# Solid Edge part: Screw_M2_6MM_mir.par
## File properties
Last saved by: hhakima
Revision: 57
Density: 7750.000 kg/m^3
Accuracy: 0.990
Material: Stainless steel
Face Style: Steel
Fill Style: ANSI32(Steel)
Virtual Style: Stainless steel
Coef. of Thermal Exp: 1.6e-05
Thermal Conductivity: 17.0
Specific Heat: 502.0
Modulus of Elasticity: 193053196000.0
Poission's Ratio: 0.29
Yield Stress: 310264065.0
Ultimate Stress: 641212401.0
Elongation: 0.0
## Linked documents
Screw_M2_6MM.par
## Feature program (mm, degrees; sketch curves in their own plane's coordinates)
part copy "CopiedPart_1"
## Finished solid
Body 1: solid body, 24 faces, 41 edges, 20 vertices.
  Faces by surface: plane 10, cone 9, cylinder 3, spline 2
  Edges by curve: circle 15, line 12, intersection 10, spline 4
Bounding box of the edges (mm; curved faces can reach further): 3.800 x 3.800 x 8.000, from (-1.9, -1.9, -8) to (1.9, 1.9, 0).
Cylindrical faces by radius (mm): R0.7402 x1, R1 x1, R1.9 x1
Conical faces (half-angle, radius in mm at the cone's reference point): 45 deg R0.866 x6, 45 deg R1.71 x1, 45 deg R1.9 x1, 55 deg R0.4862 x1
Planar faces by outward normal: +x 1, +z 2, -x 1, -z 2, oblique 4
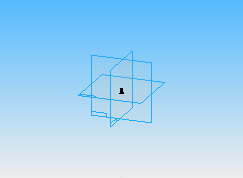
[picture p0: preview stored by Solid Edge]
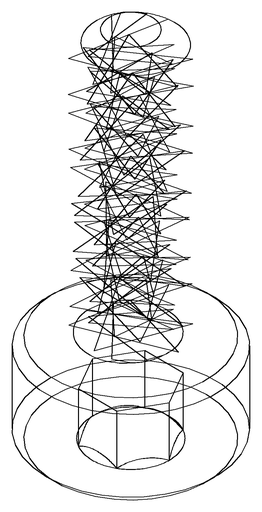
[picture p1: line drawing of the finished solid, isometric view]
